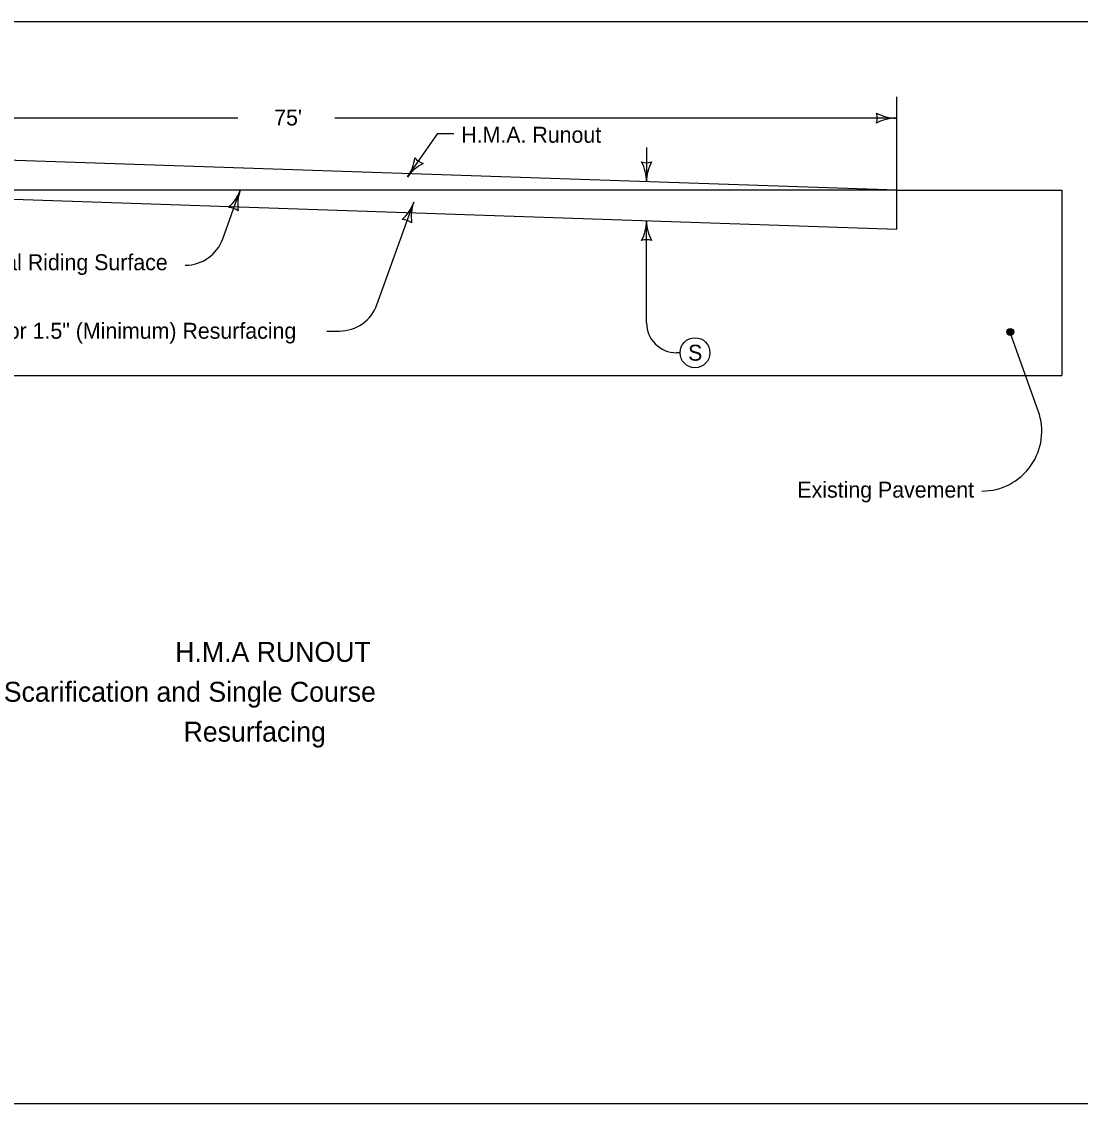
# Model space of a CAD drawing. Extents: x -2096698 to 6160, y -2144490 to 6200.
# Drawn here: x 4260 to 5322, y 4209 to 5293 of the extents above; entities that cross this region are included whole.
import ezdxf

# ---------------------------------------------------------------- set-up
doc = ezdxf.new("R2010")
doc.units = 0
for name, color, linetype in [('dsnStdLabel', 7, 'Continuous'), ('Level 15', 7, 'Continuous'), ('Level 2', 7, 'Continuous'), ('Level 3', 7, 'Continuous'), ('Level 6', 7, 'Continuous')]:
    doc.layers.add(name, color=color, linetype=linetype)

msp = doc.modelspace()

# ---------------------------------------------------------------- linework, layer by layer
at = {"layer": 'dsnStdLabel'}
for centre, radius, start, end in [((5101.6, 5196.7), 16.4, 342.2666, 17.7334), ((5137.2, 5239.2), 42.5, 241.9275, 270), ((5137.2, 5154.2), 42.5, 90, 118.0725), ((4612.1, 5162.1), 42.5, 324.8884, 352.9609), ((4681.7, 5113.2), 42.5, 116.8159, 144.8884), ((4667.4, 5166.8), 16.4, 217.155, 252.6217), ((4886.6, 5168.4), 16.4, 252.2666, 287.7333), ((4844.1, 5132.8), 42.5, 360, 28.0725), ((4929.1, 5132.8), 42.5, 151.9275, 180), ((4439.1, 5138.7), 42.5, 312.1823, 340.2547), ((4519.1, 5110), 42.5, 160.2547, 188.3272), ((4613.1, 5126.6), 42.5, 312.1823, 340.2547), ((4693.1, 5097.9), 42.5, 160.2547, 188.3272), ((4467.1, 5090.8), 16.4, 52.5214, 87.9881), ((4641, 5078.7), 16.4, 52.5214, 87.9881), ((4844.1, 5093.9), 42.5, 331.9275, 360), ((4929.1, 5093.9), 42.5, 180, 208.0725), ((4886.6, 5058.3), 16.4, 72.2666, 107.7334)]:
    msp.add_arc(centre, radius, start, end, dxfattribs=at)
at = {"layer": 'Level 15'}
for p, q in [((3074.9, 5293.4), (6131.5, 5293.4)), ((3074.9, 4209), (6131.5, 4209))]:
    msp.add_line(p, q, dxfattribs=at)
at = {"layer": 'Level 2'}
for p, q in [((5137.7, 5124.3), (5137.7, 5217.9)), ((4476.6, 5196.7), (3985.7, 5196.7)), ((5137.2, 5196.7), (4573.9, 5196.7)), ((4646.9, 5137.7), (4677.4, 5181.1)), ((4677.4, 5181.1), (4693.3, 5181.1)), ((4886.6, 5167.3), (4886.6, 5132.8)), ((4461.7, 5075.7), (4479.1, 5124.3)), ((5137.7, 5124.3), (5303, 5124.3)), ((5303, 5124.3), (5303, 4938.5)), ((4616.2, 5009.5), (4653.1, 5112.3)), ((4886.6, 4991.5), (4886.6, 5093.9)), ((4566, 4983.2), (4578.6, 4983.2)), ((5279.4, 4903.1), (5251.2, 4981.7)), ((4920.2, 4961.5), (4916.6, 4961.5)), ((3985.7, 4938.5), (5137.7, 4938.5)), ((5137.7, 4938.5), (5303, 4938.5))]:
    msp.add_line(p, q, dxfattribs=at)
msp.add_lwpolyline([(3985.7, 5124.3), (5137.7, 5085.4), (5137.7, 5124.3), (3985.7, 5124.3)], close=True, dxfattribs=at)
msp.add_lwpolyline([(5248.5, 4983.8), (5248.6, 4982.5), (5248.4, 4980.6), (5249.9, 4979.6), (5251.5, 4979.1), (5253.4, 4979.6), (5253.9, 4981.3), (5254.4, 4983.1), (5253.4, 4984.5), (5252.1, 4985.2), (5249.8, 4985), (5249.1, 4983.9), (5248.8, 4982), (5249.3, 4980.2), (5250.9, 4979.5), (5252.7, 4980), (5253.5, 4981.5), (5253.9, 4983.3), (5253, 4984), (5252, 4984.8), (5250.3, 4984.6), (5249.8, 4983.4), (5249.4, 4981.9), (5249.8, 4980.5), (5251.4, 4980.4), (5252.7, 4981.1), (5253.3, 4982.5), (5252.7, 4983.2), (5252, 4984), (5250.6, 4983.8), (5249.9, 4982.9), (5250, 4981.7), (5251, 4981.2), (5252, 4981.4), (5252.7, 4982.2), (5252.5, 4982.9), (5252, 4983.4), (5251, 4983.2), (5250.5, 4982.7), (5250.6, 4981.8), (5251.2, 4981.7), (5251.8, 4982), (5252.1, 4982.7), (5251.6, 4982.9), (5251.1, 4982.4)], dxfattribs=at)
for centre, radius in [((5251.4, 4982.3), 3.5), ((4935.2, 4961.5), 15)]:
    msp.add_circle(centre, radius, dxfattribs=at)
for centre in [(4424, 5089.2), (4578.6, 5023.2)]:
    msp.add_arc(centre, 40, 270, 340.255, dxfattribs=at)
at = {"layer": 'Level 3'}
msp.add_lwpolyline([(3985.7, 5163.2), (3525.7, 5163.2), (3525.7, 5124.3), (3985.7, 5124.3), (5137.7, 5085.4), (5137.7, 5124.3)], close=True, dxfattribs=at)
for centre, radius, start, end in [((4916.6, 4991.5), 30, 180, 270), ((5223, 4882.8), 60, 270, 19.7453)]:
    msp.add_arc(centre, radius, start, end, dxfattribs=at)

# ---------------------------------------------------------------- texts
for s, p in [("75'", (4513.2, 5189.3)), ('H.M.A. Runout', (4700.8, 5172)), ('Original Riding Surface', (4186.4, 5044.2)), ('Mill to Provide for 1.5" (Minimum) Resurfacing', (4099.7, 4975.5)), ('S', (4928.3, 4953.5)), ('Existing Pavement', (5037.9, 4816.2))]:
    msp.add_text(s, height=16, dxfattribs=at).set_placement(p)
at = {"layer": 'Level 6'}
for s, p in [('H.M.A RUNOUT', (4413.9, 4651.6)), ('Scarification and Single Course ', (4242, 4611.6)), ('Resurfacing', (4422.3, 4571.6))]:
    msp.add_text(s, height=20, dxfattribs=at).set_placement(p)

doc.saveas('drawing.dxf')
